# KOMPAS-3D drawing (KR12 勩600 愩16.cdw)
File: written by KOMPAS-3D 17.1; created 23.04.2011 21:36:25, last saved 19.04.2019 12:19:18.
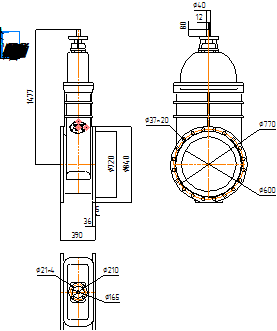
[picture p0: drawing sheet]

Sheet 1: A4, portrait

Title block, sheet 1: name: KR12 Ду600 Ру16; material: Внимание! Данный продукт является объектом авторского права ООО «Торговый Дом АДЛ». / Запрещается изменение, копирование, распространение / (в том числе путем копирования на другие сайты и ресурсы в Интернете) / или любое иное использование информации и объектов без предварительного / согласия правообладателя (ООО «Торговый Дом АДЛ»).; scale: 1:1; sheets: 1; organisation: ООО "Торговый дом АДЛ"; sheet format: A4; stored path: \\adlc.lan\data\АДЛ_ПКД\3D-модели\ADL production\Клиновые задвижки серии KR ГРАНАР\Клиновые задвижки KR12\KOMPAS 2D\KR12 Ду600 Ру16.cdw

Views: Спереди 4, Проекционный вид 5
Dimensions and other numbers on the sheet: 840; 720; 1477; 390; 36; 5; 21; 210; 165; 1:1; 1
